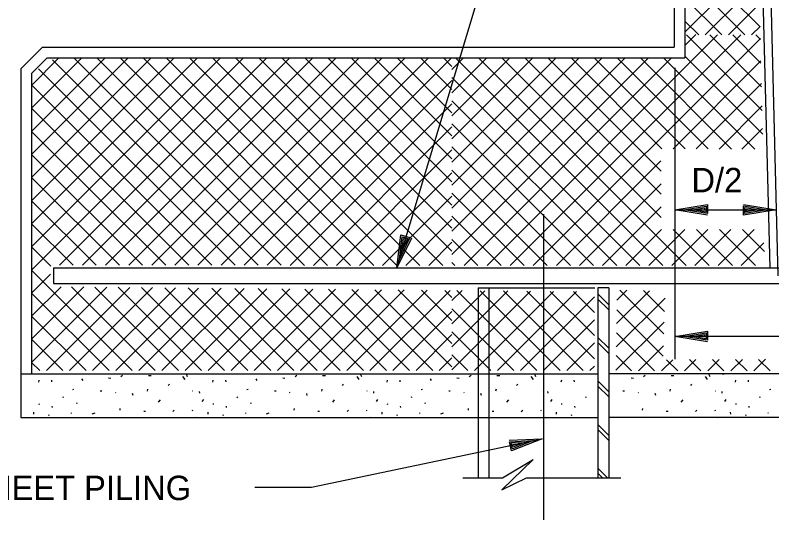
# Model space of a CAD drawing. Extents: x 44743.44 to 44747.1, y 44738.46 to 44741.29.
# Drawn here: x 44743.9931 to 44744.355, y 44740.2316 to 44740.473 of the extents above; entities that cross this region are included whole.
import ezdxf

# ---------------------------------------------------------------- set-up
doc = ezdxf.new("R2010")
doc.units = 0
for name, color, linetype in [('Level 1', 7, 'Continuous'), ('Level 10', 7, 'Continuous'), ('Level 2', 7, 'Continuous'), ('Level 7', 7, 'Continuous'), ('Level 8', 7, 'Continuous'), ('S-ANNO-TEXT', 7, 'Continuous')]:
    doc.layers.add(name, color=color, linetype=linetype)

msp = doc.modelspace()

# ---------------------------------------------------------------- linework, layer by layer
at = {"layer": 'Level 1'}
for p, q in [((44744.34866, 44740.71304), (44744.35779, 44740.34823)), ((44744.3452, 44740.46348), (44744.34931, 44740.46758)), ((44744.34947, 44740.46135), (44744.34733, 44740.46348)), ((44744.20198, 44740.4469), (44744.20755, 44740.45247)), ((44744.30857, 44740.4478), (44744.30857, 44740.30839)), ((44744.30857, 44740.37989), (44744.35699, 44740.37989)), ((44744.30857, 44740.37989), (44744.30857, 44740.37989)), ((44744.3129, 44740.37989), (44744.3129, 44740.37989)), ((44744.35266, 44740.37989), (44744.35266, 44740.37989)), ((44744.24571, 44740.37786), (44744.24571, 44740.23162)), ((44744.17685, 44740.35634), (44744.17685, 44740.35634)), ((44744.1756, 44740.35219), (44744.1756, 44740.35219)), ((44744.40224, 44740.31931), (44744.30857, 44740.31931)), ((44744.30857, 44740.31931), (44744.30857, 44740.31931)), ((44744.3129, 44740.31931), (44744.3129, 44740.31931)), ((44744.2409, 44740.26952), (44744.2409, 44740.26952)), ((44744.24514, 44740.27041), (44744.24514, 44740.27041)), ((44744.24074, 44740.26054), (44744.22584, 44740.24598)), ((44744.22622, 44740.25169), (44744.24074, 44740.26054)), ((44744.20714, 44740.25169), (44744.22622, 44740.25169)), ((44744.22584, 44740.24598), (44744.23757, 44740.25169)), ((44744.23757, 44740.25169), (44744.28277, 44740.25169))]:
    msp.add_line(p, q, dxfattribs=at)
for points in [[(44744.32415, 44740.37731), (44744.30857, 44740.37989), (44744.32415, 44740.38247), (44744.32415, 44740.37806), (44744.3129, 44740.37989), (44744.32348, 44740.38164), (44744.32348, 44740.37881), (44744.31707, 44740.37989), (44744.32282, 44740.38081), (44744.32282, 44740.37964), (44744.3214, 44740.37989)], [(44744.34141, 44740.38247), (44744.35699, 44740.37989), (44744.34141, 44740.37731), (44744.34141, 44740.38172), (44744.35266, 44740.37989), (44744.34208, 44740.37814), (44744.34208, 44740.38097), (44744.34849, 44740.37989), (44744.34274, 44740.37897), (44744.34274, 44740.38014), (44744.34416, 44740.37989)], [(44744.32415, 44740.31672), (44744.30857, 44740.31931), (44744.32415, 44740.32189), (44744.32415, 44740.31747), (44744.3129, 44740.31931), (44744.32348, 44740.32106), (44744.32348, 44740.31822), (44744.31707, 44740.31931), (44744.32282, 44740.32022), (44744.32282, 44740.31906), (44744.3214, 44740.31931)]]:
    msp.add_lwpolyline(points, dxfattribs=at)
at = {"layer": 'Level 10'}
for p, q in [((44744.30818, 44740.70744), (44744.30818, 44740.45764)), ((44743.99581, 44740.44723), (44744.00622, 44740.45764)), ((44744.00622, 44740.45764), (44744.30818, 44740.45764)), ((44743.99581, 44740.44723), (44743.99581, 44740.30145)), ((44743.99581, 44740.30145), (44744.27174, 44740.30145)), ((44744.49561, 44740.30145), (44744.27695, 44740.30145))]:
    msp.add_line(p, q, dxfattribs=at)
at = {"layer": 'Level 2'}
for p, q in [((44744.31335, 44740.70744), (44744.31335, 44740.45247)), ((44744.34506, 44740.70744), (44744.35393, 44740.35206)), ((44744.1756, 44740.35219), (44744.25626, 44740.62052)), ((44744.00097, 44740.4451), (44744.00836, 44740.45247)), ((44744.00836, 44740.45247), (44744.31335, 44740.45247)), ((44744.00097, 44740.4451), (44744.00097, 44740.30145)), ((44744.01143, 44740.35206), (44744.01143, 44740.34457)), ((44744.01143, 44740.35206), (44744.47999, 44740.35206)), ((44744.01143, 44740.34457), (44744.47999, 44740.34457)), ((44744.21447, 44740.34257), (44744.21447, 44740.28063)), ((44744.21447, 44740.34257), (44744.27035, 44740.34257)), ((44744.21968, 44740.34257), (44744.21968, 44740.25169)), ((44744.27695, 44740.34257), (44744.27174, 44740.34257)), ((44744.27174, 44740.34257), (44744.27174, 44740.25169)), ((44744.27695, 44740.34257), (44744.27695, 44740.25169)), ((44744.21447, 44740.28063), (44744.21447, 44740.25169))]:
    msp.add_line(p, q, dxfattribs=at)
for points in [[(44744.18256, 44740.36637), (44744.1756, 44740.35219), (44744.17761, 44740.36786), (44744.18184, 44740.36659), (44744.17685, 44740.35634), (44744.17821, 44740.36698), (44744.18093, 44740.36616), (44744.17805, 44740.36033), (44744.17883, 44740.3661), (44744.17994, 44740.36577), (44744.1793, 44740.36448)], [(44744.10765, 44740.24721), (44744.13483, 44740.24721), (44744.24514, 44740.27041)], [(44744.22936, 44740.26973), (44744.24514, 44740.27041), (44744.23042, 44740.26467), (44744.22951, 44740.269), (44744.2409, 44740.26952), (44744.2309, 44740.26563), (44744.23032, 44740.2684), (44744.23682, 44740.26866), (44744.23138, 44740.26658), (44744.23114, 44740.26772), (44744.23258, 44740.26777)]]:
    msp.add_lwpolyline(points, dxfattribs=at)
at = {"layer": 'Level 7'}
for p, q in [((44743.99581, 44740.30145), (44743.99581, 44740.28063)), ((44744.49561, 44740.28063), (44744.27695, 44740.28063))]:
    msp.add_line(p, q, dxfattribs=at)
at = {"layer": 'Level 8'}
for p, q in [((44744.34931, 44740.46732), (44744.31335, 44740.50328)), ((44744.31335, 44740.46476), (44744.34848, 44740.49989)), ((44744.34209, 44740.46348), (44744.31335, 44740.49223)), ((44744.32312, 44740.46348), (44744.34876, 44740.48912)), ((44744.33104, 44740.46348), (44744.31335, 44740.48117)), ((44744.33417, 44740.46348), (44744.34904, 44740.47835)), ((44744.31998, 44740.46348), (44744.31335, 44740.47011)), ((44744.21881, 44740.35329), (44744.329, 44740.46348)), ((44744.22984, 44740.35328), (44744.34005, 44740.46348)), ((44744.31856, 44740.46369), (44744.31335, 44740.45848)), ((44744.35033, 44740.42736), (44744.3142, 44740.46348)), ((44744.35005, 44740.43868), (44744.32524, 44740.46348)), ((44744.34975, 44740.45002), (44744.3363, 44740.46348)), ((44744.24089, 44740.35328), (44744.34945, 44740.46184)), ((44744.00085, 44740.43931), (44744.01401, 44740.45247)), ((44744.00097, 44740.35109), (44744.10235, 44740.45247)), ((44744.00097, 44740.36213), (44744.09131, 44740.45247)), ((44744.00097, 44740.37318), (44744.08026, 44740.45247)), ((44744.00097, 44740.38422), (44744.06922, 44740.45247)), ((44744.00097, 44740.39527), (44744.05817, 44740.45247)), ((44744.00097, 44740.40631), (44744.04713, 44740.45247)), ((44744.00097, 44740.41735), (44744.03609, 44740.45247)), ((44744.00097, 44740.4284), (44744.02505, 44740.45247)), ((44744.01429, 44740.35337), (44744.11339, 44740.45247)), ((44744.12037, 44740.35333), (44744.02116, 44740.45247)), ((44744.02533, 44740.35336), (44744.12444, 44740.45247)), ((44744.13143, 44740.35332), (44744.03221, 44740.45247)), ((44744.03637, 44740.35336), (44744.13548, 44740.45247)), ((44744.14248, 44740.35331), (44744.04327, 44740.45247)), ((44744.04741, 44740.35335), (44744.14654, 44740.45247)), ((44744.15349, 44740.35331), (44744.05433, 44740.45247)), ((44744.05844, 44740.35335), (44744.15758, 44740.45247)), ((44744.16455, 44740.35331), (44744.06538, 44740.45247)), ((44744.06949, 44740.35335), (44744.16862, 44740.45247)), ((44744.1756, 44740.35331), (44744.07642, 44740.45247)), ((44744.08052, 44740.35335), (44744.17966, 44740.45247)), ((44744.18665, 44740.3533), (44744.08747, 44740.45247)), ((44744.09157, 44740.35334), (44744.1907, 44740.45247)), ((44744.19769, 44740.3533), (44744.09851, 44740.45247)), ((44744.10261, 44740.35333), (44744.20174, 44740.45247)), ((44744.20198, 44740.36005), (44744.10957, 44740.45247)), ((44744.20198, 44740.3711), (44744.12061, 44740.45247)), ((44744.20198, 44740.38214), (44744.13165, 44740.45247)), ((44744.20198, 44740.39318), (44744.14269, 44740.45247)), ((44744.20198, 44740.40422), (44744.15373, 44740.45247)), ((44744.20198, 44740.41527), (44744.16477, 44740.45247)), ((44744.20198, 44740.42632), (44744.17582, 44740.45247)), ((44744.20198, 44740.43736), (44744.18687, 44740.45247)), ((44744.20198, 44740.44841), (44744.19791, 44740.45247)), ((44744.20198, 44740.35855), (44744.29591, 44740.45247)), ((44744.20198, 44740.3696), (44744.28486, 44740.45247)), ((44744.20198, 44740.38064), (44744.27382, 44740.45247)), ((44744.20198, 44740.39168), (44744.26279, 44740.45247)), ((44744.20198, 44740.40272), (44744.25174, 44740.45247)), ((44744.20198, 44740.41377), (44744.24068, 44740.45247)), ((44744.20198, 44740.42482), (44744.22963, 44740.45247)), ((44744.20198, 44740.43586), (44744.21859, 44740.45247)), ((44744.30288, 44740.35325), (44744.20365, 44740.45247)), ((44744.20776, 44740.35329), (44744.30695, 44740.45247)), ((44744.31394, 44740.35325), (44744.21471, 44740.45247)), ((44744.30204, 44740.3762), (44744.22576, 44740.45247)), ((44744.30199, 44740.3873), (44744.23683, 44740.45247)), ((44744.30196, 44740.39838), (44744.24788, 44740.45247)), ((44744.3023, 44740.40911), (44744.25892, 44740.45247)), ((44744.31342, 44740.40905), (44744.26998, 44740.45247)), ((44744.32452, 44740.40898), (44744.28102, 44740.45247)), ((44744.33563, 44740.40891), (44744.29208, 44740.45247)), ((44744.34674, 44740.40885), (44744.30312, 44740.45247)), ((44744.35062, 44740.41602), (44744.31335, 44740.45329)), ((44744.10931, 44740.35333), (44744.01104, 44740.45156)), ((44744.30773, 44740.40908), (44744.34972, 44740.45107)), ((44744.09824, 44740.35334), (44744.0042, 44740.44732)), ((44744.11365, 44740.35333), (44744.20198, 44740.44167)), ((44744.29182, 44740.35326), (44744.20198, 44740.44309)), ((44744.08721, 44740.35334), (44744.00134, 44740.43915)), ((44744.31871, 44740.40902), (44744.35, 44740.4403)), ((44744.12468, 44740.35332), (44744.20198, 44740.43062)), ((44744.28075, 44740.35327), (44744.20198, 44740.43203)), ((44744.07615, 44740.35335), (44744.00097, 44740.42844)), ((44744.32969, 44740.40894), (44744.35026, 44740.42953)), ((44744.26969, 44740.35327), (44744.20198, 44740.42097)), ((44744.06509, 44740.35335), (44744.00097, 44740.41739)), ((44744.13572, 44740.35332), (44744.20198, 44740.41958)), ((44744.34067, 44740.40889), (44744.35055, 44740.41876)), ((44744.25864, 44740.35327), (44744.20198, 44740.40991)), ((44744.05402, 44740.35335), (44744.00097, 44740.40633)), ((44744.14676, 44740.35331), (44744.20198, 44740.40853)), ((44744.25192, 44740.35327), (44744.30194, 44740.40329)), ((44744.24758, 44740.35327), (44744.20198, 44740.39886)), ((44744.04297, 44740.35335), (44744.00097, 44740.39529)), ((44744.15781, 44740.35331), (44744.20198, 44740.3975)), ((44744.26296, 44740.35327), (44744.30198, 44740.39228)), ((44744.23651, 44740.35328), (44744.20198, 44740.38781)), ((44744.03191, 44740.35336), (44744.00097, 44740.38423)), ((44744.16884, 44740.35331), (44744.20198, 44740.38644)), ((44744.274, 44740.35327), (44744.30202, 44740.38128)), ((44744.22546, 44740.35328), (44744.20198, 44740.37677)), ((44744.02086, 44740.35337), (44744.00097, 44740.37319)), ((44744.17989, 44740.35331), (44744.20198, 44740.3754)), ((44744.28505, 44740.35326), (44744.30222, 44740.37043)), ((44744.29608, 44740.35326), (44744.31329, 44740.37044)), ((44744.30712, 44740.35325), (44744.32434, 44740.37046)), ((44744.32499, 44740.35323), (44744.3078, 44740.37043)), ((44744.31816, 44740.35325), (44744.3354, 44740.37047)), ((44744.33606, 44740.35323), (44744.31884, 44740.37045)), ((44744.3292, 44740.35323), (44744.34646, 44740.3705)), ((44744.34712, 44740.35322), (44744.32988, 44740.37047)), ((44744.35145, 44740.35995), (44744.34091, 44740.37048)), ((44744.21443, 44740.35329), (44744.20198, 44740.36571)), ((44744.01019, 44740.353), (44744.00097, 44740.36215)), ((44744.19092, 44740.3533), (44744.20198, 44740.36436)), ((44744.34024, 44740.35323), (44744.35112, 44740.36411)), ((44744.20337, 44740.35329), (44744.20198, 44740.35467)), ((44744.04908, 44740.30298), (44744.00097, 44740.35109)), ((44744.00097, 44740.34005), (44744.01007, 44740.34914)), ((44744.00097, 44740.329), (44744.01508, 44740.34312)), ((44744.00097, 44740.31796), (44744.02601, 44740.34301)), ((44744.00097, 44740.30691), (44744.03696, 44740.34291)), ((44744.03804, 44740.30298), (44744.00097, 44740.34005)), ((44744.00808, 44740.30298), (44744.0479, 44740.3428)), ((44744.01912, 44740.30298), (44744.05884, 44740.34269)), ((44744.06012, 44740.30298), (44744.02012, 44740.34307)), ((44744.03016, 44740.30298), (44744.06977, 44740.34259)), ((44744.07116, 44740.30298), (44744.03127, 44740.34295)), ((44744.04121, 44740.30298), (44744.08071, 44740.34248)), ((44744.08221, 44740.30298), (44744.04242, 44740.34285)), ((44744.05225, 44740.30298), (44744.09165, 44740.34238)), ((44744.09326, 44740.30298), (44744.05359, 44740.34275)), ((44744.0633, 44740.30298), (44744.10259, 44740.34228)), ((44744.10432, 44740.30298), (44744.06474, 44740.34264)), ((44744.07434, 44740.30298), (44744.11352, 44740.34216)), ((44744.11538, 44740.30298), (44744.07591, 44740.34254)), ((44744.08538, 44740.30298), (44744.12446, 44740.34207)), ((44744.12643, 44740.30298), (44744.08708, 44740.34242)), ((44744.09643, 44740.30298), (44744.13541, 44740.34195)), ((44744.13748, 44740.30298), (44744.09823, 44740.34232)), ((44744.10747, 44740.30298), (44744.14635, 44740.34186)), ((44744.14854, 44740.30298), (44744.10937, 44740.3422)), ((44744.11851, 44740.30298), (44744.15729, 44740.34175)), ((44744.1596, 44740.30298), (44744.12055, 44740.3421)), ((44744.12957, 44740.30298), (44744.16822, 44740.34164)), ((44744.17066, 44740.30298), (44744.1317, 44740.342)), ((44744.1406, 44740.30298), (44744.17916, 44740.34154)), ((44744.18171, 44740.30298), (44744.14287, 44740.34189)), ((44744.15165, 44740.30298), (44744.19011, 44740.34143)), ((44744.19276, 44740.30298), (44744.15404, 44740.34179)), ((44744.16269, 44740.30298), (44744.20105, 44740.34133)), ((44744.20198, 44740.30482), (44744.16513, 44740.34167)), ((44744.20198, 44740.31588), (44744.17629, 44740.34157)), ((44744.20198, 44740.32692), (44744.18744, 44740.34145)), ((44744.20198, 44740.33796), (44744.1986, 44740.34135)), ((44744.20198, 44740.33646), (44744.2068, 44740.34128)), ((44744.20198, 44740.32541), (44744.21773, 44740.34116)), ((44744.20198, 44740.31438), (44744.22867, 44740.34107)), ((44744.20198, 44740.30333), (44744.23961, 44740.34095)), ((44744.24264, 44740.30298), (44744.20432, 44740.3413)), ((44744.21268, 44740.30298), (44744.25055, 44740.34085)), ((44744.25367, 44740.30298), (44744.21548, 44740.34119)), ((44744.22372, 44740.30298), (44744.26149, 44740.34075)), ((44744.26472, 44740.30298), (44744.22665, 44740.34108)), ((44744.27009, 44740.30865), (44744.23777, 44740.34097)), ((44744.27009, 44740.3197), (44744.24892, 44740.34087)), ((44744.27009, 44740.33077), (44744.26009, 44740.34076)), ((44744.2807, 44740.32552), (44744.29638, 44740.34119)), ((44744.28086, 44740.33671), (44744.28557, 44740.34142)), ((44744.30329, 44740.32052), (44744.28232, 44740.3415)), ((44744.30368, 44740.33118), (44744.2936, 44740.34125)), ((44744.23476, 44740.30298), (44744.27009, 44740.3383)), ((44744.27695, 44740.33447), (44744.27174, 44740.33968)), ((44744.27695, 44740.33202), (44744.27174, 44740.33722)), ((44744.28055, 44740.31432), (44744.30391, 44740.33767)), ((44744.17374, 44740.30298), (44744.20198, 44740.33122)), ((44744.23159, 44740.30298), (44744.20198, 44740.33259)), ((44744.3029, 44740.30985), (44744.28079, 44740.33197)), ((44744.02699, 44740.30298), (44744.00097, 44740.32901)), ((44744.24581, 44740.30298), (44744.27009, 44740.32726)), ((44744.2804, 44740.30312), (44744.30349, 44740.32622)), ((44744.18479, 44740.30298), (44744.20198, 44740.32018)), ((44744.22055, 44740.30298), (44744.20198, 44740.32154)), ((44744.27695, 44740.31364), (44744.27174, 44740.31885)), ((44744.29889, 44740.30283), (44744.28064, 44740.32108)), ((44744.01594, 44740.30298), (44744.00097, 44740.31795)), ((44744.25686, 44740.30298), (44744.27009, 44740.31621)), ((44744.27695, 44740.31119), (44744.27174, 44740.3164)), ((44744.29116, 44740.30283), (44744.30308, 44740.31476)), ((44744.19583, 44740.30298), (44744.20198, 44740.30914)), ((44744.2095, 44740.30298), (44744.20198, 44740.3105)), ((44744.28783, 44740.30283), (44744.28049, 44740.31017)), ((44744.30219, 44740.30283), (44744.30757, 44740.3082)), ((44744.30993, 44740.30283), (44744.30456, 44740.30819)), ((44744.31323, 44740.30283), (44744.31866, 44740.30826)), ((44744.32098, 44740.30283), (44744.31557, 44740.30823)), ((44744.32427, 44740.30283), (44744.32975, 44740.3083)), ((44744.33204, 44740.30283), (44744.32657, 44740.30829)), ((44744.33532, 44740.30282), (44744.34084, 44740.30834)), ((44744.34308, 44740.30282), (44744.33757, 44740.30833)), ((44744.34635, 44740.30282), (44744.35192, 44740.30839)), ((44744.35413, 44740.30282), (44744.34857, 44740.30837)), ((44744.0049, 44740.30298), (44744.00097, 44740.30691)), ((44744.2679, 44740.30298), (44744.27009, 44740.30517)), ((44744.04363, 44740.30012), (44744.04449, 44740.30079)), ((44744.05684, 44740.30066), (44744.0582, 44740.30067)), ((44744.0748, 44740.30145), (44744.0754, 44740.30012)), ((44744.12693, 44740.30012), (44744.1278, 44740.30079)), ((44744.14014, 44740.30066), (44744.1415, 44740.30067)), ((44744.1581, 44740.30145), (44744.15869, 44740.30012)), ((44744.21023, 44740.30012), (44744.2111, 44740.30079)), ((44744.22343, 44740.30066), (44744.22481, 44740.30067)), ((44744.24139, 44740.30145), (44744.24199, 44740.30012)), ((44744.29354, 44740.30012), (44744.2944, 44740.30079)), ((44744.30673, 44740.30066), (44744.3081, 44740.30067)), ((44744.3247, 44740.30145), (44744.3253, 44740.30012)), ((44744.33122, 44740.30145), (44744.33213, 44740.30145)), ((44744.00438, 44740.29846), (44744.0042, 44740.29747)), ((44744.01066, 44740.29755), (44744.01057, 44740.29842)), ((44744.02561, 44740.29828), (44744.02504, 44740.2991)), ((44744.03882, 44740.29917), (44744.03777, 44740.29933)), ((44744.07433, 44740.29868), (44744.07332, 44740.30016)), ((44744.08768, 44740.29846), (44744.0875, 44740.29747)), ((44744.09396, 44740.29755), (44744.09387, 44740.29842)), ((44744.10891, 44740.29828), (44744.10834, 44740.2991)), ((44744.12212, 44740.29917), (44744.12108, 44740.29933)), ((44744.15763, 44740.29868), (44744.15662, 44740.30016)), ((44744.17098, 44740.29846), (44744.17081, 44740.29747)), ((44744.17726, 44740.29755), (44744.17717, 44740.29842)), ((44744.1922, 44740.29828), (44744.19164, 44740.2991)), ((44744.20542, 44740.29917), (44744.20438, 44740.29933)), ((44744.24093, 44740.29868), (44744.23992, 44740.30016)), ((44744.25429, 44740.29846), (44744.25411, 44740.29747)), ((44744.26057, 44740.29755), (44744.26047, 44740.29842)), ((44744.27695, 44740.29282), (44744.27174, 44740.29803)), ((44744.28872, 44740.29917), (44744.28768, 44740.29933)), ((44744.32423, 44740.29868), (44744.32322, 44740.30016)), ((44744.33758, 44740.29846), (44744.33741, 44740.29747)), ((44744.34386, 44740.29755), (44744.34377, 44740.29842)), ((44744.02061, 44740.29388), (44744.02122, 44740.29408)), ((44744.03382, 44740.29333), (44744.03459, 44740.29334)), ((44744.05645, 44740.29405), (44744.05625, 44740.29308)), ((44744.06632, 44740.29582), (44744.06685, 44740.29646)), ((44744.07798, 44740.29338), (44744.07806, 44740.29329)), ((44744.08134, 44740.2922), (44744.0813, 44740.29301)), ((44744.10391, 44740.29388), (44744.10452, 44740.29408)), ((44744.11712, 44740.29333), (44744.11789, 44740.29334)), ((44744.13975, 44740.29405), (44744.13956, 44740.29308)), ((44744.14962, 44740.29582), (44744.15015, 44740.29646)), ((44744.16129, 44740.29338), (44744.16136, 44740.29329)), ((44744.16464, 44740.2922), (44744.16459, 44740.29301)), ((44744.18721, 44740.29388), (44744.18783, 44740.29408)), ((44744.20042, 44740.29333), (44744.20118, 44740.29334)), ((44744.22306, 44740.29405), (44744.22285, 44740.29308)), ((44744.23291, 44740.29582), (44744.23345, 44740.29646)), ((44744.24459, 44740.29338), (44744.24466, 44740.29329)), ((44744.24794, 44740.2922), (44744.24789, 44740.29301)), ((44744.27695, 44740.29037), (44744.27174, 44740.29558)), ((44744.28372, 44740.29333), (44744.28448, 44740.29334)), ((44744.30635, 44740.29405), (44744.30615, 44740.29308)), ((44744.31621, 44740.29582), (44744.31674, 44740.29646)), ((44744.32789, 44740.29338), (44744.32796, 44740.29329)), ((44744.33124, 44740.2922), (44744.33119, 44740.29301)), ((44744.35381, 44740.29388), (44744.35442, 44740.29408)), ((44744.01621, 44740.28995), (44744.01602, 44740.2904)), ((44744.04126, 44740.29239), (44744.04107, 44740.29255)), ((44744.04951, 44740.29115), (44744.04924, 44740.29202)), ((44744.09951, 44740.28995), (44744.09933, 44740.2904)), ((44744.12457, 44740.29239), (44744.12437, 44740.29255)), ((44744.13282, 44740.29115), (44744.13255, 44740.29202)), ((44744.18281, 44740.28995), (44744.18263, 44740.2904)), ((44744.20787, 44740.29239), (44744.20767, 44740.29255)), ((44744.21611, 44740.29115), (44744.21585, 44740.29202)), ((44744.26611, 44740.28995), (44744.26593, 44740.2904)), ((44744.29117, 44740.29239), (44744.29096, 44740.29255)), ((44744.29941, 44740.29115), (44744.29915, 44740.29202)), ((44744.34941, 44740.28995), (44744.34922, 44740.2904)), ((44744.00463, 44740.28686), (44744.00468, 44740.2872)), ((44744.01094, 44740.2854), (44744.01085, 44740.28603)), ((44744.02254, 44740.28727), (44744.0227, 44740.28769)), ((44744.06168, 44740.28784), (44744.06259, 44740.28905)), ((44744.08261, 44740.28817), (44744.08325, 44740.28912)), ((44744.08793, 44740.28686), (44744.08798, 44740.2872)), ((44744.09424, 44740.2854), (44744.09415, 44740.28603)), ((44744.10584, 44740.28727), (44744.106, 44740.28769)), ((44744.14498, 44740.28784), (44744.14589, 44740.28905)), ((44744.16591, 44740.28817), (44744.16656, 44740.28912)), ((44744.17123, 44740.28686), (44744.17129, 44740.2872)), ((44744.17755, 44740.2854), (44744.17744, 44740.28603)), ((44744.18913, 44740.28727), (44744.1893, 44740.28769)), ((44744.22829, 44740.28784), (44744.22919, 44740.28905)), ((44744.24921, 44740.28817), (44744.24986, 44740.28912)), ((44744.25454, 44740.28686), (44744.25458, 44740.2872)), ((44744.26085, 44740.2854), (44744.26074, 44740.28603)), ((44744.31159, 44740.28784), (44744.31249, 44740.28905)), ((44744.3325, 44740.28817), (44744.33316, 44740.28912)), ((44744.33783, 44740.28686), (44744.33788, 44740.2872)), ((44744.34415, 44740.2854), (44744.34405, 44740.28603)), ((44744.00207, 44740.28217), (44744.00205, 44740.2831)), ((44744.02009, 44740.28241), (44744.02005, 44740.28286)), ((44744.03, 44740.28235), (44744.03131, 44740.28279)), ((44744.04326, 44740.28411), (44744.04332, 44740.28489)), ((44744.05458, 44740.2836), (44744.0554, 44740.28362)), ((44744.06852, 44740.2834), (44744.0692, 44740.28415)), ((44744.07806, 44740.2839), (44744.07765, 44740.28383)), ((44744.08537, 44740.28217), (44744.08535, 44740.2831)), ((44744.10339, 44740.28241), (44744.10334, 44740.28286)), ((44744.11331, 44740.28235), (44744.11461, 44740.28279)), ((44744.12657, 44740.28411), (44744.12662, 44740.28489)), ((44744.13788, 44740.2836), (44744.1387, 44740.28362)), ((44744.15183, 44740.2834), (44744.15249, 44740.28415)), ((44744.16135, 44740.2839), (44744.16095, 44740.28383)), ((44744.16867, 44740.28217), (44744.16865, 44740.2831)), ((44744.18669, 44740.28241), (44744.18664, 44740.28286)), ((44744.19661, 44740.28235), (44744.1979, 44740.28279)), ((44744.20987, 44740.28411), (44744.20992, 44740.28489)), ((44744.22118, 44740.2836), (44744.222, 44740.28362)), ((44744.23512, 44740.2834), (44744.2358, 44740.28415)), ((44744.24465, 44740.2839), (44744.24425, 44740.28383)), ((44744.25196, 44740.28217), (44744.25195, 44740.2831)), ((44744.29316, 44740.28411), (44744.29321, 44740.28489)), ((44744.30447, 44740.2836), (44744.30531, 44740.28362)), ((44744.31842, 44740.2834), (44744.3191, 44740.28415)), ((44744.32795, 44740.2839), (44744.32756, 44740.28383)), ((44744.33526, 44740.28217), (44744.33525, 44740.2831)), ((44744.3533, 44740.28241), (44744.35324, 44740.28286)), ((44744.00941, 44740.2814), (44744.00923, 44740.28186)), ((44744.07911, 44740.28063), (44744.07994, 44740.2807)), ((44744.09271, 44740.2814), (44744.09254, 44740.28186)), ((44744.16241, 44740.28063), (44744.16324, 44740.2807)), ((44744.17601, 44740.2814), (44744.17584, 44740.28186)), ((44744.24571, 44740.28063), (44744.24655, 44740.2807)), ((44744.25932, 44740.2814), (44744.25914, 44740.28186)), ((44744.32901, 44740.28063), (44744.32985, 44740.2807)), ((44744.34261, 44740.2814), (44744.34244, 44740.28186)), ((44744.27695, 44740.272), (44744.27174, 44740.2772)), ((44744.27695, 44740.26955), (44744.27174, 44740.27476)), ((44744.27643, 44740.25169), (44744.27174, 44740.25637)), ((44744.27397, 44740.25169), (44744.27174, 44740.25392))]:
    msp.add_line(p, q, dxfattribs=at)
at = {"layer": 'S-ANNO-TEXT'}
msp.add_line((44743.99581, 44740.28063), (44744.27174, 44740.28063), dxfattribs=at)

# ---------------------------------------------------------------- texts
for s, height, p in [('D/2', 0.011667, (44744.31651, 44740.38826)), ('C/L SHEET PILING', 0.0116667, (44743.94113, 44740.24106))]:
    msp.add_text(s, height=height, dxfattribs=at).set_placement(p)

doc.saveas('drawing.dxf')
